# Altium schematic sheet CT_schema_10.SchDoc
size 385 x 278 mm
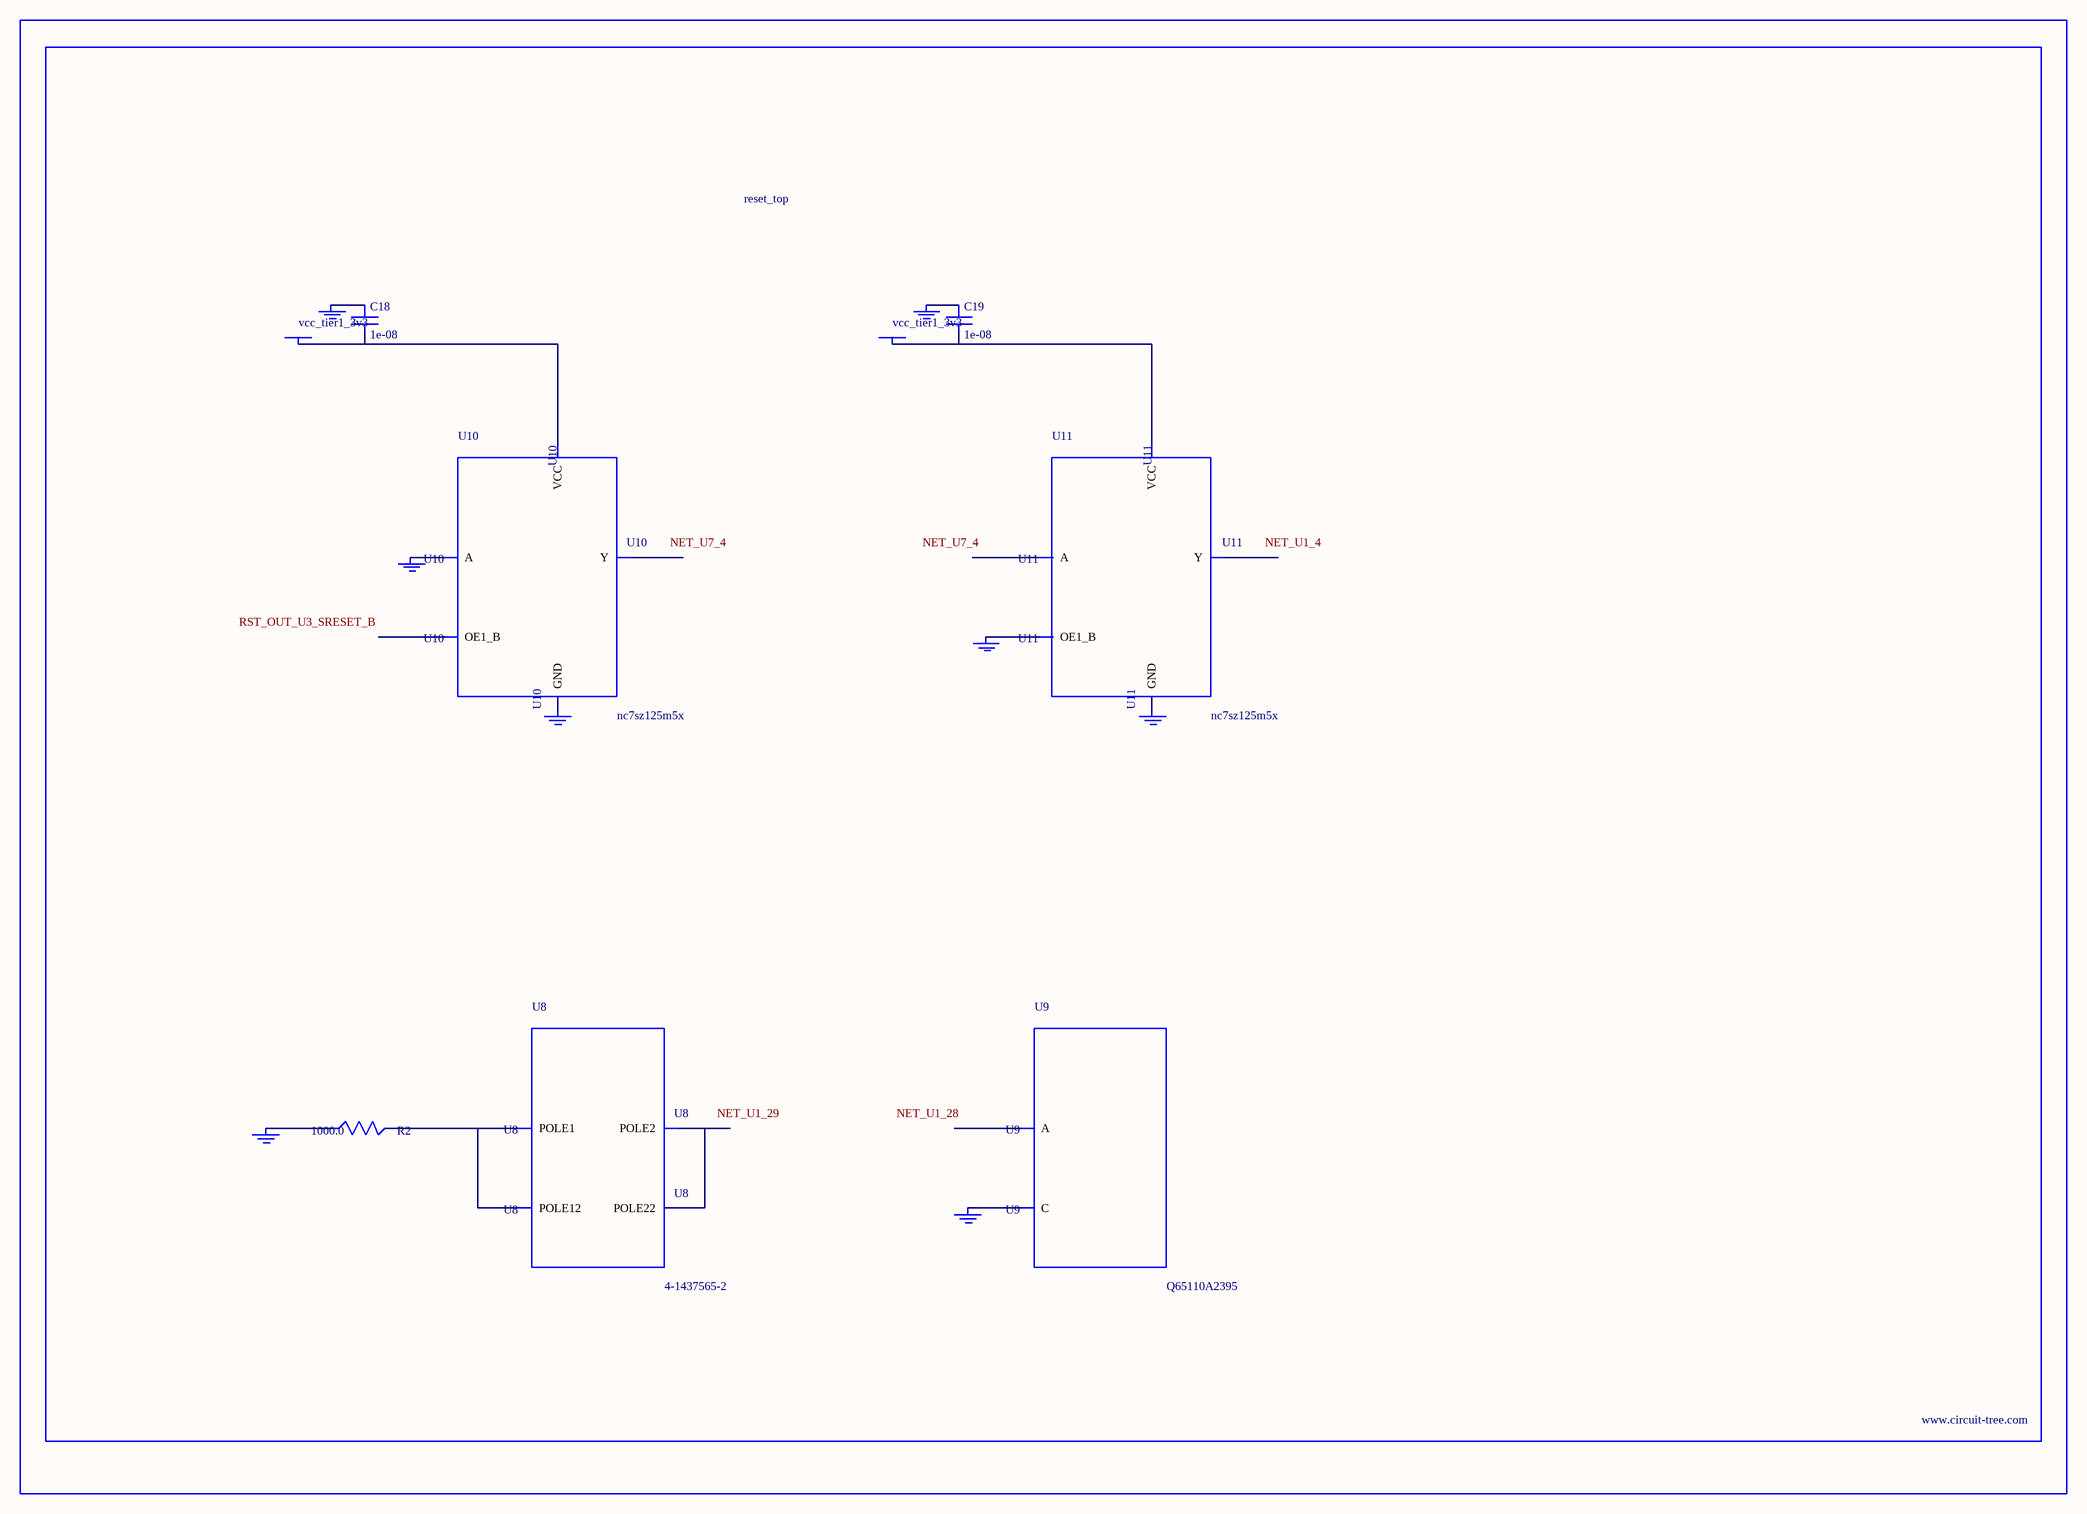
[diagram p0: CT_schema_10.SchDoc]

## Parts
BORDER9  (no value)
C18  1e-08  [C0402]
C19  1e-08  [C0402]
GND_INSTANCE_9_0  (no value)
GND_INSTANCE_9_1  (no value)
GND_INSTANCE_9_2  (no value)
GND_INSTANCE_9_3  (no value)
GND_INSTANCE_9_4  (no value)
GND_INSTANCE_9_5  (no value)
GND_INSTANCE_9_6  (no value)
GND_INSTANCE_9_7  (no value)
POWER_INSTANCE_9_0  vcc_tier1_3v3
POWER_INSTANCE_9_1  vcc_tier1_3v3
R2  1000.0  [R0603]
U8  4-1437565-2  [SW_4-1437565-2]
U9  Q65110A2395  [LGM67K-G1J2-24-Z]
U10  nc7sz125m5x  [NC7SZ125M5X]
U11  nc7sz125m5x  [NC7SZ125M5X]

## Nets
NetC18_1: C18.1 GND_INSTANCE_9_2.0(GND)
NetC18_2: C18.2 POWER_INSTANCE_9_0.0(PWR) U10.5(VCC)
NetC19_1: C19.1 GND_INSTANCE_9_5.0(GND)
NetC19_2: C19.2 POWER_INSTANCE_9_1.0(PWR) U11.5(VCC)
NetGND_INSTANCE_9_0_0: GND_INSTANCE_9_0.0(GND) R2.1
NetGND_INSTANCE_9_1_0: GND_INSTANCE_9_1.0(GND) U9.C
NetGND_INSTANCE_9_3_0: GND_INSTANCE_9_3.0(GND) U10.2(A)
NetGND_INSTANCE_9_4_0: GND_INSTANCE_9_4.0(GND) U10.3(GND)
NetGND_INSTANCE_9_6_0: GND_INSTANCE_9_6.0(GND) U11.1(OE1_B)
NetGND_INSTANCE_9_7_0: GND_INSTANCE_9_7.0(GND) U11.3(GND)
NetR2_2: R2.2 U8.1(POLE1) U8.2(POLE12)
NetU8_3: U8.3(POLE2) U8.4(POLE22)

Not connected (* = marked no-connect by the designer): U9 A; U10 1(OE1_B) 4(Y); U11 2(A) 4(Y)

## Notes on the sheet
- Labels drawn without touching a wire or pin: NET_U1_4, NET_U1_28, NET_U1_29, NET_U7_4, RST_OUT_U3_SRESET_B

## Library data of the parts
BORDER9 = BORDER_PAGE9
C18 C19 = C0402C103K3RAC
GND_INSTANCE_9_0-GND_INSTANCE_9_7 = GND
POWER_INSTANCE_9_0 POWER_INSTANCE_9_1 = PWR
R2 = RC0603JR-071KL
